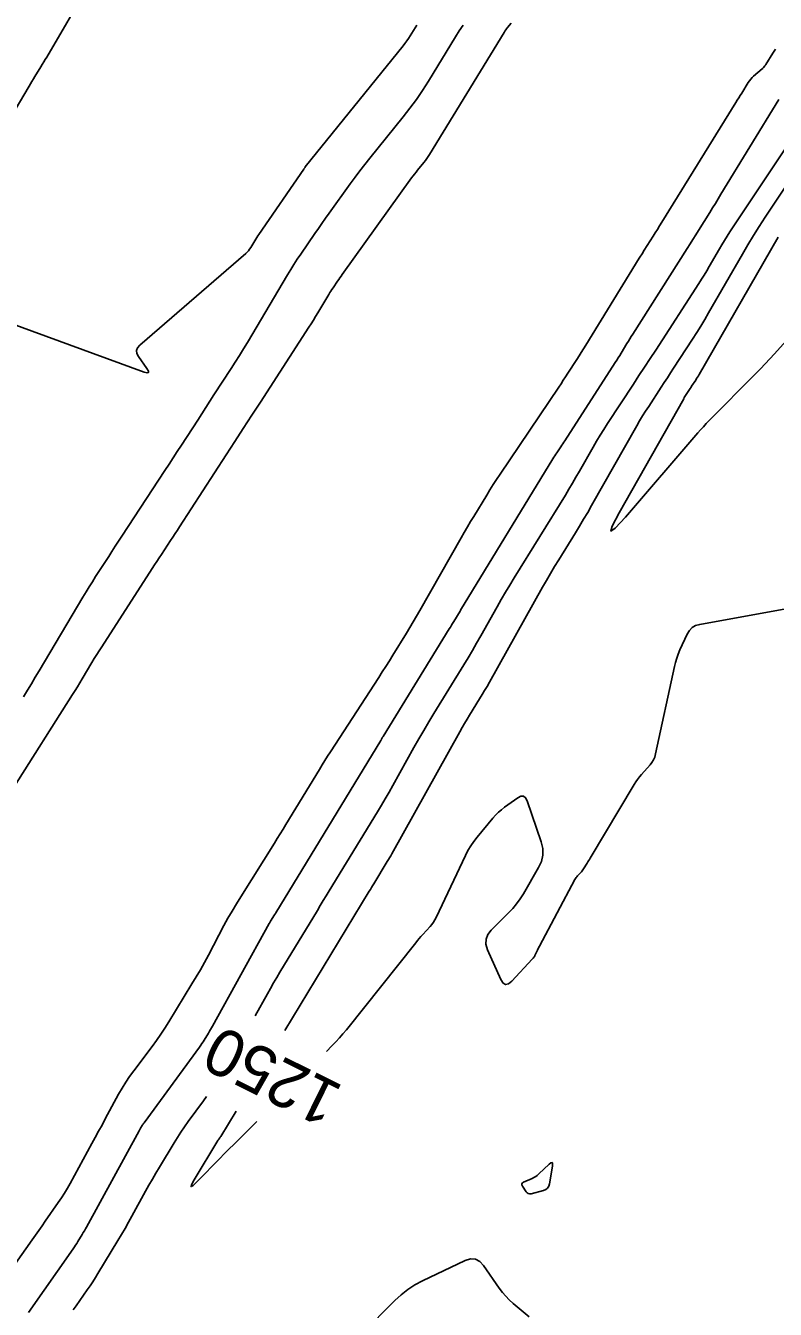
# Model space of a CAD drawing. Extents: x 658976 to 668721, y 639543 to 647196.
# Drawn here: x 661893.9 to 661989.7, y 641412.7 to 641576.8 of the extents above; entities that cross this region are included whole.
import ezdxf

# ---------------------------------------------------------------- set-up
doc = ezdxf.new("R2010")
doc.units = 0
for name, color, linetype in [('Ex_Contour Labels', 7, 'Continuous'), ('Ex_Major Contours', 7, 'Continuous'), ('Ex_Minor Contours', 7, 'Continuous')]:
    doc.layers.add(name, color=color, linetype=linetype)

msp = doc.modelspace()

# ---------------------------------------------------------------- linework, layer by layer
at = {"layer": 'Ex_Major Contours'}
for points in [[(661992.76, 641558.8), (661988.43, 641552.27), (661987.67, 641551.1), (661986.93, 641549.93), (661986.21, 641548.74), (661985.51, 641547.55), (661981.19, 641540.05), (661980.69, 641539.2), (661980.18, 641538.36), (661979.67, 641537.53), (661979.14, 641536.7), (661976.72, 641532.98), (661976.33, 641532.37), (661975.93, 641531.76), (661975.53, 641531.15), (661975.13, 641530.54), (661973.53, 641528.1), (661973.13, 641527.49), (661972.75, 641526.87), (661972.37, 641526.24), (661972.01, 641525.61), (661966.24, 641515.42), (661965.74, 641514.54), (661965.22, 641513.67), (661964.7, 641512.8), (661964.17, 641511.93), (661962.04, 641508.47), (661961.51, 641507.61), (661960.99, 641506.74), (661960.48, 641505.86), (661959.98, 641504.98), (661953.17, 641492.85), (661952.87, 641492.31), (661952.56, 641491.78), (661952.24, 641491.25), (661951.92, 641490.73), (661950.64, 641488.63), (661950.32, 641488.1), (661950, 641487.58), (661949.7, 641487.04), (661949.39, 641486.51), (661940.7, 641470.89), (661940.56, 641470.64), (661940.42, 641470.4), (661940.28, 641470.16), (661940.13, 641469.91), (661938.4, 641467.06), (661938.25, 641466.83), (661938.11, 641466.6), (661937.97, 641466.36), (661937.83, 641466.13), (661927.02, 641448.31)], [(661932.36, 641445.66), (661933.06, 641446.36), (661933.54, 641446.86), (661934.01, 641447.37), (661934.46, 641447.89), (661934.9, 641448.43), (661943.76, 641459.55), (661943.98, 641459.81), (661944.2, 641460.08), (661944.43, 641460.34), (661944.66, 641460.6), (661945.6, 641461.62), (661945.82, 641461.89), (661946.02, 641462.16), (661946.2, 641462.46), (661946.36, 641462.76), (661950.12, 641470.71), (661950.44, 641471.33), (661950.79, 641471.92), (661951.18, 641472.49), (661951.61, 641473.04), (661953.61, 641475.46), (661953.95, 641475.85), (661954.32, 641476.21), (661954.71, 641476.55), (661955.12, 641476.86), (661956.81, 641478.06), (661957.2, 641478.26), (661957.53, 641478.26), (661957.8, 641478.07), (661958, 641477.67), (661959.8, 641472.42), (661960, 641471.57), (661960.01, 641470.75), (661959.84, 641469.94), (661959.47, 641469.15), (661957.52, 641465.8), (661957.11, 641465.15), (661956.66, 641464.52), (661956.17, 641463.93), (661955.63, 641463.36), (661953.42, 641461.17), (661952.98, 641460.6), (661952.75, 641459.99), (661952.74, 641459.34), (661952.95, 641458.65), (661954.63, 641454.85), (661954.92, 641454.39), (661955.25, 641454.19), (661955.63, 641454.27), (661956.05, 641454.62), (661958.65, 641457.44), (661958.69, 641457.47), (661958.72, 641457.51), (661958.75, 641457.55), (661958.78, 641457.58), (661958.9, 641457.73), (661958.93, 641457.76), (661958.96, 641457.8), (661958.98, 641457.84), (661959, 641457.89), (661959.32, 641458.59), (661959.38, 641458.72), (661959.44, 641458.85), (661959.51, 641458.98), (661959.57, 641459.11), (661964.1, 641467.62), (661964.18, 641467.75), (661964.26, 641467.87), (661964.35, 641467.98), (661964.45, 641468.09), (661964.86, 641468.51), (661964.95, 641468.61), (661965.05, 641468.73), (661965.13, 641468.84), (661965.21, 641468.97), (661965.66, 641469.7), (661965.76, 641469.87), (661965.86, 641470.03), (661965.96, 641470.19), (661966.06, 641470.36), (661971.68, 641479.75), (661971.89, 641480.09), (661972.12, 641480.42), (661972.37, 641480.74), (661972.63, 641481.05), (661973.7, 641482.27), (661973.95, 641482.58), (661974.15, 641482.92), (661974.3, 641483.28), (661974.41, 641483.67), (661976.81, 641494.84), (661976.94, 641495.38), (661977.11, 641495.92), (661977.3, 641496.44), (661977.52, 641496.96), (661978.47, 641499), (661978.74, 641499.46), (661979.1, 641499.82), (661979.53, 641500.07), (661980.05, 641500.22), (661992.45, 641502.47)], [(661920.81, 641438), (661918.84, 641434.78), (661918.81, 641434.74), (661918.79, 641434.7), (661918.76, 641434.65), (661918.72, 641434.61), (661918.6, 641434.44), (661918.57, 641434.39), (661918.54, 641434.35), (661918.51, 641434.31), (661918.48, 641434.26), (661915.44, 641429.22), (661915.11, 641428.62), (661915.05, 641428.38), (661915.27, 641428.49), (661915.77, 641428.97), (661918.8, 641432.07), (661919.2, 641432.48), (661919.61, 641432.89), (661920.01, 641433.29), (661920.42, 641433.69), (661922.06, 641435.3), (661922.47, 641435.7), (661922.88, 641436.11), (661923.28, 641436.51), (661923.46, 641436.69)]]:
    msp.add_lwpolyline(points, dxfattribs=at)
at = {"layer": 'Ex_Minor Contours'}
for points in [[(661888.1, 641558.49), (661894.35, 641569.01), (661894.54, 641569.32), (661894.72, 641569.63), (661894.91, 641569.95), (661895.1, 641570.26), (661895.85, 641571.49), (661896.04, 641571.81), (661896.23, 641572.12), (661896.41, 641572.43), (661896.6, 641572.74), (661902.05, 641582.07)], [(661943.89, 641576.83), (661943.06, 641575.47), (661942.85, 641575.13), (661942.63, 641574.8), (661942.39, 641574.48), (661942.15, 641574.17), (661929.65, 641558.69), (661929.63, 641558.67), (661929.62, 641558.64), (661929.6, 641558.62), (661929.58, 641558.6), (661929.51, 641558.5), (661929.5, 641558.48), (661929.48, 641558.45), (661929.46, 641558.43), (661929.45, 641558.4), (661923.73, 641550.08), (661923.58, 641549.88), (661923.45, 641549.67), (661923.31, 641549.45), (661923.18, 641549.24), (661922.67, 641548.38), (661922.54, 641548.17), (661922.38, 641547.97), (661922.22, 641547.79), (661922.04, 641547.62), (661908.5, 641535.9), (661908.21, 641535.58), (661908.09, 641535.24), (661908.12, 641534.87), (661908.32, 641534.49), (661909.42, 641532.92), (661909.6, 641532.59), (661909.6, 641532.41), (661909.43, 641532.37), (661909.07, 641532.46), (661879.13, 641543.41)], [(661955.96, 641577.09), (661955.48, 641576.5), (661955.37, 641576.35), (661955.26, 641576.2), (661955.15, 641576.04), (661955.05, 641575.89), (661945.52, 641560.29), (661945.35, 641560.03), (661945.17, 641559.77), (661944.99, 641559.52), (661944.79, 641559.27), (661944, 641558.29), (661943.81, 641558.04), (661943.62, 641557.79), (661943.43, 641557.54), (661943.24, 641557.29), (661934.36, 641544.93), (661934.22, 641544.72), (661934.07, 641544.52), (661933.92, 641544.31), (661933.78, 641544.1), (661933.21, 641543.26), (661933.06, 641543.05), (661932.92, 641542.84), (661932.79, 641542.63), (661932.66, 641542.41), (661931.25, 641540.05), (661930.97, 641539.58), (661930.69, 641539.12), (661930.4, 641538.66), (661930.11, 641538.2), (661923.91, 641528.63), (661922.82, 641526.95), (661921.73, 641525.27), (661920.64, 641523.59), (661919.55, 641521.91), (661913.59, 641512.72), (661913.3, 641512.27), (661913.01, 641511.83), (661912.72, 641511.38), (661912.43, 641510.94), (661911.26, 641509.16), (661910.97, 641508.72), (661910.68, 641508.27), (661910.39, 641507.83), (661910.1, 641507.38), (661903.63, 641497.38), (661903.3, 641496.87), (661902.99, 641496.37), (661902.68, 641495.86), (661902.37, 641495.35), (661901.15, 641493.29), (661900.84, 641492.78), (661900.53, 641492.27), (661900.22, 641491.76), (661899.9, 641491.26), (661892.18, 641479.07)], [(661949.82, 641576.82), (661949.32, 641576.09), (661948.85, 641575.33), (661945.38, 641569.67), (661944.63, 641568.48), (661943.84, 641567.33), (661943.02, 641566.19), (661942.15, 641565.09), (661937.91, 641559.83), (661937.27, 641559.02), (661936.63, 641558.2), (661936.01, 641557.37), (661935.4, 641556.54), (661932.7, 641552.77), (661932.24, 641552.13), (661931.78, 641551.48), (661931.33, 641550.83), (661930.87, 641550.18), (661929.08, 641547.56), (661928.63, 641546.91), (661928.2, 641546.24), (661927.78, 641545.57), (661927.37, 641544.89), (661922.25, 641536.28), (661921.74, 641535.43), (661921.22, 641534.59), (661920.7, 641533.75), (661920.16, 641532.92), (661917.98, 641529.56), (661917.46, 641528.75), (661916.94, 641527.95), (661916.42, 641527.14), (661915.9, 641526.34), (661913.81, 641523.12), (661913.28, 641522.31), (661912.76, 641521.51), (661912.24, 641520.7), (661911.71, 641519.9), (661906.2, 641511.49), (661905.78, 641510.85), (661905.36, 641510.21), (661904.94, 641509.56), (661904.53, 641508.92), (661902.86, 641506.34), (661902.44, 641505.69), (661902.03, 641505.04), (661901.63, 641504.39), (661901.24, 641503.73), (661895.64, 641494.3), (661895.14, 641493.47), (661894.64, 641492.64), (661894.13, 641491.81), (661893.62, 641490.99)], [(661892.61, 641418.54), (661894.76, 641421.58), (661895.18, 641422.17), (661895.59, 641422.76), (661896.01, 641423.36), (661896.42, 641423.95), (661898.08, 641426.33), (661898.49, 641426.92), (661898.88, 641427.53), (661899.25, 641428.16), (661899.61, 641428.79), (661902.38, 641433.88), (661902.81, 641434.66), (661903.24, 641435.45), (661903.67, 641436.24), (661904.09, 641437.02), (661905.79, 641440.17), (661906.23, 641440.95), (661906.7, 641441.71), (661907.2, 641442.45), (661907.72, 641443.17), (661910.07, 641446.3), (661910.63, 641447.06), (661911.17, 641447.84), (661911.7, 641448.63), (661912.2, 641449.44), (661915.15, 641454.27), (661915.7, 641455.18), (661916.24, 641456.1), (661916.76, 641457.03), (661917.26, 641457.97), (661919.26, 641461.73), (661919.77, 641462.67), (661920.3, 641463.59), (661920.84, 641464.51), (661921.4, 641465.42), (661925.7, 641472.28), (661926.07, 641472.88), (661926.44, 641473.47), (661926.81, 641474.07), (661927.17, 641474.67), (661931.45, 641481.7), (661931.79, 641482.26), (661932.15, 641482.83), (661932.5, 641483.39), (661932.87, 641483.96), (661939.04, 641493.46), (661939.49, 641494.16), (661939.94, 641494.86), (661940.39, 641495.57), (661940.82, 641496.28), (661942.57, 641499.12), (661943, 641499.84), (661943.43, 641500.55), (661943.85, 641501.27), (661944.27, 641502), (661949.56, 641511.3), (661949.96, 641511.99), (661950.36, 641512.68), (661950.76, 641513.36), (661951.17, 641514.04), (661952.83, 641516.75), (661953.24, 641517.43), (661953.67, 641518.1), (661954.1, 641518.76), (661954.54, 641519.42), (661962.03, 641530.54), (661962.33, 641530.98), (661962.62, 641531.43), (661962.91, 641531.87), (661963.2, 641532.32), (661964.35, 641534.1), (661964.64, 641534.55), (661964.92, 641535), (661965.2, 641535.45), (661965.48, 641535.9), (661971.84, 641546.25), (661972.12, 641546.7), (661972.4, 641547.15), (661972.68, 641547.6), (661972.96, 641548.05), (661974.09, 641549.83), (661974.37, 641550.27), (661974.65, 641550.72), (661974.93, 641551.17), (661975.21, 641551.62), (661984.68, 641566.92), (661984.86, 641567.22), (661985.05, 641567.53), (661985.24, 641567.83), (661985.42, 641568.13), (661986.26, 641569.5), (661986.41, 641569.72), (661986.57, 641569.93), (661986.75, 641570.12), (661986.94, 641570.29), (661988.05, 641571.24), (661988.1, 641571.28), (661988.14, 641571.32), (661988.18, 641571.36), (661988.22, 641571.41), (661988.37, 641571.6), (661988.41, 641571.65), (661988.45, 641571.7), (661988.48, 641571.75), (661988.52, 641571.81), (661989.4, 641573.24), (661989.56, 641573.49), (661989.72, 641573.75)], [(661894.29, 641412.29), (661899.99, 641420.44), (661900.14, 641420.66), (661900.29, 641420.89), (661900.44, 641421.12), (661900.58, 641421.35), (661901.14, 641422.27), (661901.28, 641422.5), (661901.42, 641422.74), (661901.55, 641422.97), (661901.68, 641423.21), (661908.4, 641435.5), (661908.45, 641435.59), (661908.5, 641435.67), (661908.55, 641435.76), (661908.6, 641435.85), (661908.81, 641436.19), (661908.86, 641436.28), (661908.92, 641436.37), (661908.98, 641436.45), (661909.04, 641436.53), (661916.14, 641446.21), (661916.29, 641446.43), (661916.44, 641446.65), (661916.58, 641446.87), (661916.72, 641447.09), (661917.27, 641447.99), (661917.41, 641448.22), (661917.54, 641448.44), (661917.67, 641448.67), (661917.8, 641448.9), (661925.03, 641461.98), (661925.07, 641462.06), (661925.12, 641462.13), (661925.16, 641462.2), (661925.2, 641462.28), (661925.71, 641463.11), (661925.75, 641463.17), (661925.79, 641463.24), (661925.83, 641463.3), (661925.87, 641463.37), (661939.3, 641485.4), (661939.33, 641485.44), (661939.35, 641485.49), (661939.37, 641485.53), (661939.4, 641485.57), (661939.49, 641485.73), (661939.51, 641485.77), (661939.53, 641485.81), (661939.56, 641485.85), (661939.58, 641485.89), (661948.05, 641499.67), (661948.19, 641499.89), (661948.33, 641500.12), (661948.47, 641500.35), (661948.61, 641500.58), (661949.45, 641501.94), (661949.46, 641501.96), (661949.47, 641501.97), (661949.48, 641502), (661949.49, 641502.02), (661949.5, 641502.03), (661961.3, 641521.39), (661961.42, 641521.59), (661961.55, 641521.78), (661961.67, 641521.98), (661961.8, 641522.17), (661962.32, 641522.94), (661962.45, 641523.13), (661962.57, 641523.32), (661962.7, 641523.51), (661962.82, 641523.71), (661969.26, 641533.72), (661969.45, 641534.01), (661969.64, 641534.31), (661969.83, 641534.61), (661970.01, 641534.91), (661970.75, 641536.12), (661970.94, 641536.42), (661971.12, 641536.72), (661971.31, 641537.02), (661971.5, 641537.31), (661978.47, 641548.28), (661978.83, 641548.85), (661979.19, 641549.42), (661979.55, 641550), (661979.91, 641550.58), (661981.34, 641552.89), (661981.69, 641553.46), (661982.05, 641554.04), (661982.4, 641554.62), (661982.76, 641555.2), (661990.16, 641567.3)], [(661923.25, 641450.19), (661924.8, 641453.01), (661925.19, 641453.71), (661925.59, 641454.41), (661926, 641455.1), (661926.41, 641455.79), (661931.19, 641463.67), (661931.57, 641464.29), (661931.95, 641464.92), (661932.33, 641465.54), (661932.71, 641466.17), (661938.88, 641476.29), (661939.38, 641477.12), (661939.87, 641477.95), (661940.36, 641478.79), (661940.83, 641479.63), (661943.54, 641484.51), (661944.16, 641485.6), (661944.79, 641486.68), (661945.42, 641487.76), (661946.07, 641488.83), (661949.9, 641495.06), (661950.46, 641495.97), (661951.01, 641496.89), (661951.54, 641497.82), (661952.07, 641498.75), (661954.17, 641502.48), (661954.7, 641503.41), (661955.23, 641504.34), (661955.78, 641505.26), (661956.34, 641506.17), (661962.88, 641516.76), (661963.34, 641517.51), (661963.8, 641518.27), (661964.24, 641519.03), (661964.68, 641519.8), (661966.42, 641522.87), (661966.87, 641523.64), (661967.32, 641524.4), (661967.79, 641525.15), (661968.26, 641525.89), (661971.58, 641530.94), (661972.29, 641532.03), (661973, 641533.12), (661973.72, 641534.21), (661974.43, 641535.3), (661979.94, 641543.8), (661980.29, 641544.34), (661980.63, 641544.88), (661980.96, 641545.43), (661981.28, 641545.99), (661982.56, 641548.21), (661982.89, 641548.76), (661983.22, 641549.31), (661983.56, 641549.85), (661983.91, 641550.39), (661992.83, 641563.83)], [(661990.08, 641549.72), (661979.98, 641532.18), (661979.88, 641532), (661979.77, 641531.82), (661979.65, 641531.64), (661979.54, 641531.46), (661979.02, 641530.66), (661978.94, 641530.53), (661978.85, 641530.4), (661978.76, 641530.27), (661978.68, 641530.14), (661978.33, 641529.61), (661978.25, 641529.48), (661978.16, 641529.35), (661978.08, 641529.21), (661978.01, 641529.08), (661969.75, 641514.49), (661968.86, 641512.79), (661968.7, 641512.13), (661969.26, 641512.51), (661970.56, 641513.92), (661979.82, 641524.71), (661980.17, 641525.11), (661980.53, 641525.5), (661980.89, 641525.89), (661981.27, 641526.28), (661987.2, 641532.27), (661987.8, 641532.9), (661988.41, 641533.53), (661989, 641534.16), (661989.59, 641534.81), (661993.74, 641539.4)], [(661900, 641412.63), (661900.35, 641413.14), (661901.78, 641415.19), (661902.14, 641415.7), (661902.48, 641416.22), (661902.82, 641416.74), (661903.15, 641417.28), (661905.7, 641421.47), (661906.16, 641422.25), (661906.62, 641423.02), (661907.06, 641423.81), (661907.5, 641424.59), (661909.24, 641427.79), (661909.67, 641428.56), (661910.11, 641429.32), (661910.55, 641430.08), (661911, 641430.84), (661912.88, 641433.95), (661913.31, 641434.65), (661913.76, 641435.34), (661914.22, 641436.02), (661914.7, 641436.69), (661916.64, 641439.34), (661917.03, 641439.88)], [(661958.27, 641411.75), (661956.22, 641413.45), (661955.72, 641413.89), (661955.26, 641414.36), (661954.83, 641414.86), (661954.44, 641415.39), (661952.44, 641418.28), (661951.95, 641418.81), (661951.39, 641419.1), (661950.76, 641419.13), (661950.07, 641418.91), (661944.61, 641416.32), (661943.65, 641415.81), (661942.74, 641415.22), (661941.89, 641414.56), (661941.09, 641413.82), (661936.92, 641409.59)]]:
    msp.add_lwpolyline(points, dxfattribs=at)
msp.add_lwpolyline([(661958.86, 641429.52), (661959.09, 641429.66), (661959.3, 641429.81), (661959.49, 641429.99), (661960.8, 641431.23), (661961.04, 641431.42), (661961.19, 641431.45), (661961.26, 641431.31), (661961.24, 641431), (661960.85, 641428.73), (661960.76, 641428.42), (661960.6, 641428.18), (661960.37, 641428), (661960.08, 641427.88), (661958.5, 641427.47), (661958.31, 641427.45), (661958.14, 641427.48), (661957.99, 641427.57), (661957.86, 641427.72), (661957.4, 641428.42), (661957.32, 641428.58), (661957.32, 641428.72), (661957.4, 641428.84), (661957.55, 641428.94), (661958.63, 641429.41)], close=True, dxfattribs=at)

# ---------------------------------------------------------------- texts
at = {"layer": 'Ex_Contour Labels'}
msp.add_text('1250', height=6, rotation=153.5352, dxfattribs=at).set_placement((661934.72, 641441.13))

doc.saveas('drawing.dxf')
